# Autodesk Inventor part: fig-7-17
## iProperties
Created: 2004-05
Part Number: fig-7-17
Document SubType Name: Modeling
Designer: CADCIM Technologies
Manufacturer: Standard
Standards Organization: Custom
Author: CADCIM Technologies
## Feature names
1. Extrusion1
